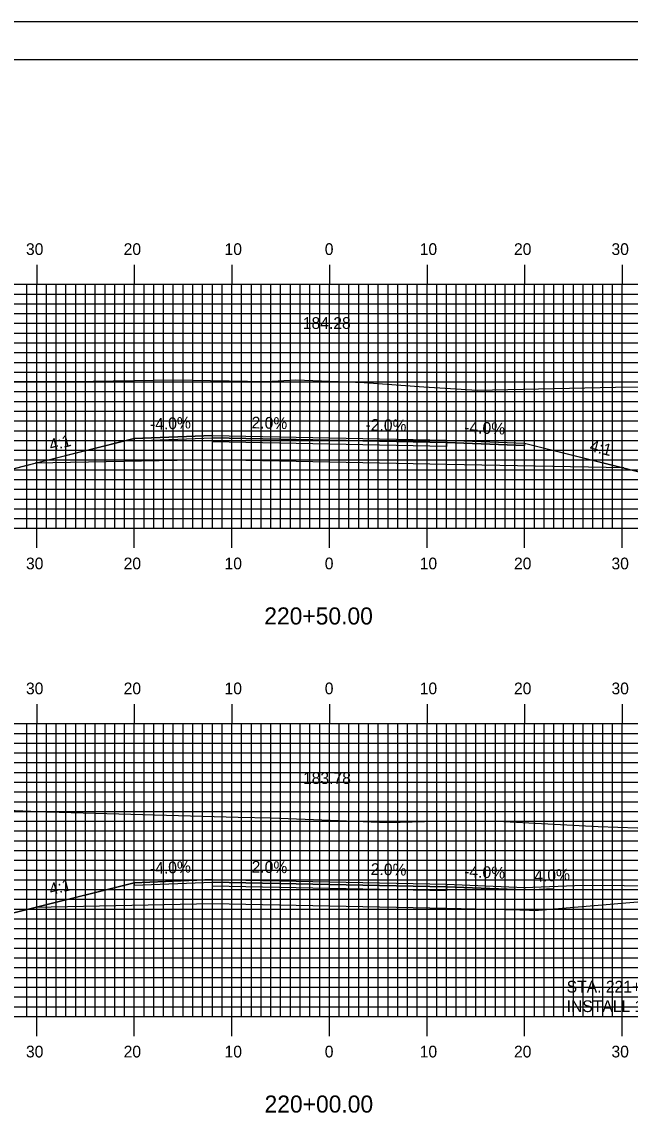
# Model space of a CAD drawing. Extents: x 1797207 to 1797550, y 442591 to 442811.
# Drawn here: x 1797341.4 to 1797403.7, y 442698.5 to 442810.5 of the extents above; entities that cross this region are included whole.
import ezdxf

# ---------------------------------------------------------------- set-up
doc = ezdxf.new("R2010")
doc.units = 0
for name, color, linetype in [('ANNOTATION', 7, 'Continuous'), ('BORDER', 7, 'Continuous'), ('D_Roadway_Centerline', 7, 'Continuous'), ('D_Roadway_Centerline_Text', 7, 'Continuous'), ('D_Roadway_Edge_Shoulder', 7, 'Continuous'), ('D_Roadway_Edge_TW', 7, 'Continuous'), ('D_Roadway_Pavement', 7, 'Continuous'), ('D_Roadway_SlopeLines', 7, 'Continuous'), ('D_Roadway_SubGrade', 7, 'Continuous'), ('H_V ANNOTATION', 7, 'Continuous'), ('MAJOR', 7, 'Continuous'), ('MINOR', 7, 'Continuous'), ('PLOT BOUNDARY', 7, 'Continuous'), ('S_Roadway_Centerline', 7, 'Continuous')]:
    doc.layers.add(name, color=color, linetype=linetype)

msp = doc.modelspace()

# ---------------------------------------------------------------- linework, layer by layer
at = {"layer": 'BORDER'}
msp.add_lwpolyline([(1797223.33, 442596.67), (1797543.33, 442596.67), (1797543.33, 442806.67), (1797223.33, 442806.67)], close=True, dxfattribs=at)
at = {"layer": 'D_Roadway_Centerline'}
for points in [[(1797294.18, 442774.92), (1797295.43, 442774.81), (1797296.68, 442774.55), (1797297.93, 442774.15), (1797299.18, 442773.6), (1797310.36, 442768.01), (1797324.58, 442767.87), (1797338.76, 442764.33), (1797342.76, 442765.33), (1797352.93, 442767.87), (1797360.93, 442768.19), (1797372.93, 442767.95), (1797384.93, 442767.71), (1797392.93, 442767.39), (1797403.11, 442764.85), (1797407.11, 442763.85), (1797421.28, 442767.39), (1797440.76, 442767.58), (1797446.68, 442770.54), (1797447.93, 442771.08), (1797449.18, 442771.45), (1797450.43, 442771.65), (1797451.68, 442771.68)], [(1797282.93, 442731.5), (1797284.18, 442731.38), (1797285.43, 442731.11), (1797286.68, 442730.7), (1797287.93, 442730.15), (1797303.2, 442722.51), (1797317.5, 442722.37), (1797338.76, 442718.83), (1797342.76, 442719.83), (1797352.93, 442722.37), (1797360.93, 442722.69), (1797372.93, 442722.45), (1797384.93, 442722.21), (1797392.93, 442721.89)]]:
    msp.add_lwpolyline(points, dxfattribs=at)
at = {"layer": 'D_Roadway_Edge_Shoulder'}
for points in [[(1797360.93, 442768.19), (1797352.93, 442767.87), (1797352.93, 442767.62), (1797360.93, 442767.94)], [(1797384.93, 442767.71), (1797392.93, 442767.39), (1797392.93, 442767.14), (1797384.93, 442767.46)], [(1797360.93, 442722.69), (1797352.93, 442722.37), (1797352.93, 442722.12), (1797360.93, 442722.44)], [(1797384.93, 442722.21), (1797392.93, 442721.89), (1797392.93, 442721.64), (1797384.93, 442721.96)]]:
    msp.add_lwpolyline(points, close=True, dxfattribs=at)
at = {"layer": 'D_Roadway_Edge_TW'}
for points in [[(1797360.93, 442767.94), (1797360.93, 442768.19), (1797372.93, 442767.95), (1797384.93, 442767.71), (1797384.93, 442767.46), (1797372.93, 442767.7)], [(1797360.93, 442722.44), (1797360.93, 442722.69), (1797372.93, 442722.45), (1797384.93, 442722.21), (1797384.93, 442721.96), (1797372.93, 442722.2)]]:
    msp.add_lwpolyline(points, close=True, dxfattribs=at)
at = {"layer": 'D_Roadway_Pavement'}
for points in [[(1797360.93, 442767.52), (1797360.93, 442767.94), (1797372.93, 442767.7), (1797384.93, 442767.46), (1797384.93, 442767.04), (1797372.93, 442767.28)], [(1797360.93, 442722.02), (1797360.93, 442722.44), (1797372.93, 442722.2), (1797384.93, 442721.96), (1797384.93, 442721.54), (1797372.93, 442721.78)]]:
    msp.add_lwpolyline(points, close=True, dxfattribs=at)
at = {"layer": 'D_Roadway_SlopeLines'}
for points in [[(1797352.93, 442767.87), (1797338.76, 442764.33)], [(1797392.93, 442767.39), (1797407.11, 442763.85)], [(1797352.93, 442722.37), (1797338.76, 442718.83)]]:
    msp.add_lwpolyline(points, dxfattribs=at)
at = {"layer": 'D_Roadway_SubGrade'}
msp.add_line((1797392.93, 442721.64), (1797395.93, 442721.76), dxfattribs=at)
msp.add_lwpolyline([(1797360.93, 442765.69), (1797342.76, 442765.33), (1797352.93, 442767.87), (1797352.93, 442767.62), (1797360.93, 442767.94), (1797372.93, 442767.7), (1797384.93, 442767.46), (1797392.93, 442767.14), (1797392.93, 442767.39), (1797403.11, 442764.85), (1797384.93, 442765.21), (1797372.93, 442765.45)], close=True, dxfattribs=at)
for points in [[(1797393.93, 442719.53), (1797384.93, 442719.71), (1797372.93, 442719.95), (1797360.93, 442720.19), (1797342.76, 442719.83), (1797352.93, 442722.37), (1797352.93, 442722.12), (1797360.93, 442722.44), (1797372.93, 442722.2), (1797384.93, 442721.96), (1797392.93, 442721.64), (1797392.93, 442721.89)], [(1797392.93, 442721.89), (1797398.93, 442722.13), (1797428.37, 442721.89)], [(1797395.93, 442721.76), (1797395.93, 442722.01)], [(1797393.43, 442719.54), (1797393.93, 442719.53), (1797404.93, 442720.46), (1797419.07, 442720.34)]]:
    msp.add_lwpolyline(points, dxfattribs=at)
at = {"layer": 'MAJOR'}
for p, q in [((1797342.93, 442785.67), (1797342.93, 442783.67)), ((1797352.93, 442785.67), (1797352.93, 442783.67)), ((1797362.93, 442785.67), (1797362.93, 442783.67)), ((1797372.93, 442785.67), (1797372.93, 442783.67)), ((1797382.93, 442785.67), (1797382.93, 442783.67)), ((1797392.93, 442785.67), (1797392.93, 442783.67)), ((1797402.93, 442785.67), (1797402.93, 442783.67)), ((1797232.93, 442783.67), (1797512.93, 442783.67)), ((1797232.93, 442783.67), (1797512.93, 442783.67)), ((1797342.93, 442758.67), (1797342.93, 442783.67)), ((1797352.93, 442758.67), (1797352.93, 442783.67)), ((1797362.93, 442758.67), (1797362.93, 442783.67)), ((1797372.93, 442758.67), (1797372.93, 442783.67)), ((1797382.93, 442758.67), (1797382.93, 442783.67)), ((1797392.93, 442758.67), (1797392.93, 442783.67)), ((1797402.93, 442758.67), (1797402.93, 442783.67)), ((1797232.93, 442778.67), (1797512.93, 442778.67)), ((1797232.93, 442773.67), (1797512.93, 442773.67)), ((1797232.93, 442768.67), (1797512.93, 442768.67)), ((1797232.93, 442763.67), (1797512.93, 442763.67)), ((1797232.93, 442758.67), (1797512.93, 442758.67)), ((1797232.93, 442758.67), (1797512.93, 442758.67)), ((1797342.93, 442756.66), (1797342.93, 442758.67)), ((1797352.93, 442756.66), (1797352.93, 442758.67)), ((1797362.93, 442756.66), (1797362.93, 442758.67)), ((1797372.93, 442756.66), (1797372.93, 442758.67)), ((1797382.93, 442756.66), (1797382.93, 442758.67)), ((1797392.93, 442756.66), (1797392.93, 442758.67)), ((1797402.93, 442756.66), (1797402.93, 442758.67)), ((1797342.93, 442740.67), (1797342.93, 442738.67)), ((1797352.93, 442740.67), (1797352.93, 442738.67)), ((1797362.93, 442740.67), (1797362.93, 442738.67)), ((1797372.93, 442740.67), (1797372.93, 442738.67)), ((1797382.93, 442740.67), (1797382.93, 442738.67)), ((1797392.93, 442740.67), (1797392.93, 442738.67)), ((1797402.93, 442740.67), (1797402.93, 442738.67)), ((1797232.93, 442738.67), (1797512.93, 442738.67)), ((1797232.93, 442738.67), (1797512.93, 442738.67)), ((1797342.93, 442708.67), (1797342.93, 442738.67)), ((1797352.93, 442708.67), (1797352.93, 442738.67)), ((1797362.93, 442708.67), (1797362.93, 442738.67)), ((1797372.93, 442708.67), (1797372.93, 442738.67)), ((1797382.93, 442708.67), (1797382.93, 442738.67)), ((1797392.93, 442708.67), (1797392.93, 442738.67)), ((1797402.93, 442708.67), (1797402.93, 442738.67)), ((1797232.93, 442733.67), (1797512.93, 442733.67)), ((1797232.93, 442728.67), (1797512.93, 442728.67)), ((1797232.93, 442723.67), (1797512.93, 442723.67)), ((1797232.93, 442718.67), (1797512.93, 442718.67)), ((1797232.93, 442713.67), (1797512.93, 442713.67)), ((1797232.93, 442708.67), (1797512.93, 442708.67)), ((1797232.93, 442708.67), (1797512.93, 442708.67)), ((1797342.93, 442706.66), (1797342.93, 442708.67)), ((1797352.93, 442706.66), (1797352.93, 442708.67)), ((1797362.93, 442706.66), (1797362.93, 442708.67)), ((1797372.93, 442706.66), (1797372.93, 442708.67)), ((1797382.93, 442706.66), (1797382.93, 442708.67)), ((1797392.93, 442706.66), (1797392.93, 442708.67)), ((1797402.93, 442706.66), (1797402.93, 442708.67))]:
    msp.add_line(p, q, dxfattribs=at)
at = {"layer": 'MINOR'}
for p, q in [((1797341.93, 442758.67), (1797341.93, 442783.67)), ((1797343.93, 442758.67), (1797343.93, 442783.67)), ((1797344.93, 442758.67), (1797344.93, 442783.67)), ((1797345.93, 442758.67), (1797345.93, 442783.67)), ((1797346.93, 442758.67), (1797346.93, 442783.67)), ((1797347.93, 442758.67), (1797347.93, 442783.67)), ((1797348.93, 442758.67), (1797348.93, 442783.67)), ((1797349.93, 442758.67), (1797349.93, 442783.67)), ((1797350.93, 442758.67), (1797350.93, 442783.67)), ((1797351.93, 442758.67), (1797351.93, 442783.67)), ((1797353.93, 442758.67), (1797353.93, 442783.67)), ((1797354.93, 442758.67), (1797354.93, 442783.67)), ((1797355.93, 442758.67), (1797355.93, 442783.67)), ((1797356.93, 442758.67), (1797356.93, 442783.67)), ((1797357.93, 442758.67), (1797357.93, 442783.67)), ((1797358.93, 442758.67), (1797358.93, 442783.67)), ((1797359.93, 442758.67), (1797359.93, 442783.67)), ((1797360.93, 442758.67), (1797360.93, 442783.67)), ((1797361.93, 442758.67), (1797361.93, 442783.67)), ((1797363.93, 442758.67), (1797363.93, 442783.67)), ((1797364.93, 442758.67), (1797364.93, 442783.67)), ((1797365.93, 442758.67), (1797365.93, 442783.67)), ((1797366.93, 442758.67), (1797366.93, 442783.67)), ((1797367.93, 442758.67), (1797367.93, 442783.67)), ((1797368.93, 442758.67), (1797368.93, 442783.67)), ((1797369.93, 442758.67), (1797369.93, 442783.67)), ((1797370.93, 442758.67), (1797370.93, 442783.67)), ((1797371.93, 442758.67), (1797371.93, 442783.67)), ((1797373.93, 442758.67), (1797373.93, 442783.67)), ((1797374.93, 442758.67), (1797374.93, 442783.67)), ((1797375.93, 442758.67), (1797375.93, 442783.67)), ((1797376.93, 442758.67), (1797376.93, 442783.67)), ((1797377.93, 442758.67), (1797377.93, 442783.67)), ((1797378.93, 442758.67), (1797378.93, 442783.67)), ((1797379.93, 442758.67), (1797379.93, 442783.67)), ((1797380.93, 442758.67), (1797380.93, 442783.67)), ((1797381.93, 442758.67), (1797381.93, 442783.67)), ((1797383.93, 442758.67), (1797383.93, 442783.67)), ((1797384.93, 442758.67), (1797384.93, 442783.67)), ((1797385.93, 442758.67), (1797385.93, 442783.67)), ((1797386.93, 442758.67), (1797386.93, 442783.67)), ((1797387.93, 442758.67), (1797387.93, 442783.67)), ((1797388.93, 442758.67), (1797388.93, 442783.67)), ((1797389.93, 442758.67), (1797389.93, 442783.67)), ((1797390.93, 442758.67), (1797390.93, 442783.67)), ((1797391.93, 442758.67), (1797391.93, 442783.67)), ((1797393.93, 442758.67), (1797393.93, 442783.67)), ((1797394.93, 442758.67), (1797394.93, 442783.67)), ((1797395.93, 442758.67), (1797395.93, 442783.67)), ((1797396.93, 442758.67), (1797396.93, 442783.67)), ((1797397.93, 442758.67), (1797397.93, 442783.67)), ((1797398.93, 442758.67), (1797398.93, 442783.67)), ((1797399.93, 442758.67), (1797399.93, 442783.67)), ((1797400.93, 442758.67), (1797400.93, 442783.67)), ((1797401.93, 442758.67), (1797401.93, 442783.67)), ((1797232.93, 442782.67), (1797512.93, 442782.67)), ((1797232.93, 442781.67), (1797512.93, 442781.67)), ((1797232.93, 442780.67), (1797512.93, 442780.67)), ((1797232.93, 442779.67), (1797512.93, 442779.67)), ((1797232.93, 442777.67), (1797512.93, 442777.67)), ((1797232.93, 442776.67), (1797512.93, 442776.67)), ((1797232.93, 442775.67), (1797512.93, 442775.67)), ((1797232.93, 442774.67), (1797512.93, 442774.67)), ((1797232.93, 442772.67), (1797512.93, 442772.67)), ((1797232.93, 442771.67), (1797512.93, 442771.67)), ((1797232.93, 442770.67), (1797512.93, 442770.67)), ((1797232.93, 442769.67), (1797512.93, 442769.67)), ((1797232.93, 442767.67), (1797512.93, 442767.67)), ((1797232.93, 442766.67), (1797512.93, 442766.67)), ((1797232.93, 442765.67), (1797512.93, 442765.67)), ((1797232.93, 442764.67), (1797512.93, 442764.67)), ((1797232.93, 442762.67), (1797512.93, 442762.67)), ((1797232.93, 442761.67), (1797512.93, 442761.67)), ((1797232.93, 442760.67), (1797512.93, 442760.67)), ((1797232.93, 442759.67), (1797512.93, 442759.67)), ((1797341.93, 442708.67), (1797341.93, 442738.67)), ((1797343.93, 442708.67), (1797343.93, 442738.67)), ((1797344.93, 442708.67), (1797344.93, 442738.67)), ((1797345.93, 442708.67), (1797345.93, 442738.67)), ((1797346.93, 442708.67), (1797346.93, 442738.67)), ((1797347.93, 442708.67), (1797347.93, 442738.67)), ((1797348.93, 442708.67), (1797348.93, 442738.67)), ((1797349.93, 442708.67), (1797349.93, 442738.67)), ((1797350.93, 442708.67), (1797350.93, 442738.67)), ((1797351.93, 442708.67), (1797351.93, 442738.67)), ((1797353.93, 442708.67), (1797353.93, 442738.67)), ((1797354.93, 442708.67), (1797354.93, 442738.67)), ((1797355.93, 442708.67), (1797355.93, 442738.67)), ((1797356.93, 442708.67), (1797356.93, 442738.67)), ((1797357.93, 442708.67), (1797357.93, 442738.67)), ((1797358.93, 442708.67), (1797358.93, 442738.67)), ((1797359.93, 442708.67), (1797359.93, 442738.67)), ((1797360.93, 442708.67), (1797360.93, 442738.67)), ((1797361.93, 442708.67), (1797361.93, 442738.67)), ((1797363.93, 442708.67), (1797363.93, 442738.67)), ((1797364.93, 442708.67), (1797364.93, 442738.67)), ((1797365.93, 442708.67), (1797365.93, 442738.67)), ((1797366.93, 442708.67), (1797366.93, 442738.67)), ((1797367.93, 442708.67), (1797367.93, 442738.67)), ((1797368.93, 442708.67), (1797368.93, 442738.67)), ((1797369.93, 442708.67), (1797369.93, 442738.67)), ((1797370.93, 442708.67), (1797370.93, 442738.67)), ((1797371.93, 442708.67), (1797371.93, 442738.67)), ((1797373.93, 442708.67), (1797373.93, 442738.67)), ((1797374.93, 442708.67), (1797374.93, 442738.67)), ((1797375.93, 442708.67), (1797375.93, 442738.67)), ((1797376.93, 442708.67), (1797376.93, 442738.67)), ((1797377.93, 442708.67), (1797377.93, 442738.67)), ((1797378.93, 442708.67), (1797378.93, 442738.67)), ((1797379.93, 442708.67), (1797379.93, 442738.67)), ((1797380.93, 442708.67), (1797380.93, 442738.67)), ((1797381.93, 442708.67), (1797381.93, 442738.67)), ((1797383.93, 442708.67), (1797383.93, 442738.67)), ((1797384.93, 442708.67), (1797384.93, 442738.67)), ((1797385.93, 442708.67), (1797385.93, 442738.67)), ((1797386.93, 442708.67), (1797386.93, 442738.67)), ((1797387.93, 442708.67), (1797387.93, 442738.67)), ((1797388.93, 442708.67), (1797388.93, 442738.67)), ((1797389.93, 442708.67), (1797389.93, 442738.67)), ((1797390.93, 442708.67), (1797390.93, 442738.67)), ((1797391.93, 442708.67), (1797391.93, 442738.67)), ((1797393.93, 442708.67), (1797393.93, 442738.67)), ((1797394.93, 442708.67), (1797394.93, 442738.67)), ((1797395.93, 442708.67), (1797395.93, 442738.67)), ((1797396.93, 442708.67), (1797396.93, 442738.67)), ((1797397.93, 442708.67), (1797397.93, 442738.67)), ((1797398.93, 442708.67), (1797398.93, 442738.67)), ((1797399.93, 442708.67), (1797399.93, 442738.67)), ((1797400.93, 442708.67), (1797400.93, 442738.67)), ((1797401.93, 442708.67), (1797401.93, 442738.67)), ((1797232.93, 442737.67), (1797512.93, 442737.67)), ((1797232.93, 442736.67), (1797512.93, 442736.67)), ((1797232.93, 442735.67), (1797512.93, 442735.67)), ((1797232.93, 442734.67), (1797512.93, 442734.67)), ((1797232.93, 442732.67), (1797512.93, 442732.67)), ((1797232.93, 442731.67), (1797512.93, 442731.67)), ((1797232.93, 442730.67), (1797512.93, 442730.67)), ((1797232.93, 442729.67), (1797512.93, 442729.67)), ((1797232.93, 442727.67), (1797512.93, 442727.67)), ((1797232.93, 442726.67), (1797512.93, 442726.67)), ((1797232.93, 442725.67), (1797512.93, 442725.67)), ((1797232.93, 442724.67), (1797512.93, 442724.67)), ((1797232.93, 442722.67), (1797512.93, 442722.67)), ((1797232.93, 442721.67), (1797512.93, 442721.67)), ((1797232.93, 442720.67), (1797512.93, 442720.67)), ((1797232.93, 442719.67), (1797512.93, 442719.67)), ((1797232.93, 442717.67), (1797512.93, 442717.67)), ((1797232.93, 442716.67), (1797512.93, 442716.67)), ((1797232.93, 442715.67), (1797512.93, 442715.67)), ((1797232.93, 442714.67), (1797512.93, 442714.67)), ((1797232.93, 442712.67), (1797512.93, 442712.67)), ((1797232.93, 442711.67), (1797512.93, 442711.67)), ((1797232.93, 442710.67), (1797512.93, 442710.67)), ((1797232.93, 442709.67), (1797512.93, 442709.67))]:
    msp.add_line(p, q, dxfattribs=at)
at = {"layer": 'PLOT BOUNDARY'}
msp.add_lwpolyline([(1797207.14, 442590.55), (1797547.14, 442590.55), (1797547.14, 442810.55), (1797207.14, 442810.55)], close=True, dxfattribs=at)
at = {"layer": 'S_Roadway_Centerline'}
for points in [[(1797338.85, 442773.76), (1797346.65, 442773.7), (1797356.94, 442773.88), (1797366.43, 442773.72), (1797369.5, 442773.89), (1797376.5, 442773.61), (1797382.61, 442773.17), (1797388.07, 442772.81), (1797402.23, 442773.12), (1797407.7, 442773.21), (1797408.6, 442773.19), (1797410.01, 442773.08), (1797420.37, 442772.1), (1797428.58, 442772.22), (1797432.61, 442772.33), (1797438.13, 442772.23), (1797445.15, 442772.08), (1797449.51, 442771.77), (1797463.24, 442771.2), (1797470.07, 442771.1)], [(1797331.86, 442730.14), (1797343.1, 442729.66), (1797343.99, 442729.62), (1797345.24, 442729.58), (1797363.56, 442729.09), (1797366.97, 442729), (1797371.3, 442728.84), (1797378.9, 442728.53), (1797383.95, 442728.67), (1797390.15, 442728.68), (1797400.45, 442728.11), (1797404.48, 442727.99), (1797422.18, 442727.99), (1797424.47, 442727.99), (1797424.67, 442728), (1797424.96, 442728), (1797437.25, 442727.65), (1797445.58, 442727.73), (1797449.83, 442727.56), (1797455.01, 442727.25), (1797461.14, 442726.89), (1797466.94, 442726.6)]]:
    msp.add_lwpolyline(points, dxfattribs=at)

# ---------------------------------------------------------------- texts
at = {"layer": 'ANNOTATION'}
for s, rotation, p in [('-4.0%', 2.2906, (1797354.56, 442768.74)), ('2.0%', 358.8542, (1797364.94, 442768.91)), ('-2.0%', 358.8542, (1797376.62, 442768.68)), ('-4.0%', 357.7094, (1797386.72, 442768.44)), ('4:1', 14.0362, (1797344.38, 442766.59)), ('4:1', 345.9638, (1797399.52, 442766.6)), ('2.0%', 358.8542, (1797364.94, 442723.41)), ('-4.0%', 2.2906, (1797354.56, 442723.24)), ('-2.0%', 358.8542, (1797376.62, 442723.18)), ('-4.0%', 357.7094, (1797386.72, 442722.94)), ('4.0%', 2.2906, (1797393.94, 442722.46)), ('4:1', 14.0362, (1797344.38, 442721.09))]:
    msp.add_text(s, height=1.2, rotation=rotation, dxfattribs=at).set_placement(p)
for s, p in [("STA. 221+88.00, 34.4' RT. TO 222+12.00, 34.2' RT.", (1797397.24, 442711.12)), ('INSTALL 18" X 24\' OPT. I CULVERT PIPE', (1797397.24, 442709.12))]:
    msp.add_text(s, height=1.2, dxfattribs=at).set_placement(p)
at = {"layer": 'D_Roadway_Centerline'}
for s, p in [('C', (1797372.93, 442767.95)), ('L', (1797372.93, 442767.94)), ('C', (1797372.93, 442722.45)), ('L', (1797372.93, 442722.44))]:
    msp.add_text(s, height=0.0146, dxfattribs=at).set_placement(p)
at = {"layer": 'D_Roadway_Centerline_Text'}
for s, p in [('184.28', (1797370.2, 442779.1)), ('183.78', (1797370.22, 442732.48))]:
    msp.add_text(s, height=1.2, dxfattribs=at).set_placement(p)
at = {"layer": 'H_V ANNOTATION'}
for s, height, p in [('30', 1.2, (1797341.83, 442786.67)), ('20', 1.2, (1797351.84, 442786.67)), ('10', 1.2, (1797362.18, 442786.67)), ('0', 1.2, (1797372.45, 442786.67)), ('10', 1.2, (1797382.18, 442786.67)), ('20', 1.2, (1797391.84, 442786.67)), ('30', 1.2, (1797401.83, 442786.67)), ('30', 1.2, (1797341.83, 442754.47)), ('20', 1.2, (1797351.84, 442754.47)), ('10', 1.2, (1797362.18, 442754.47)), ('0', 1.2, (1797372.45, 442754.47)), ('10', 1.2, (1797382.18, 442754.47)), ('20', 1.2, (1797391.84, 442754.47)), ('30', 1.2, (1797401.83, 442754.47)), ('220+50.00', 1.75, (1797366.25, 442748.82)), ('30', 1.2, (1797341.83, 442741.67)), ('20', 1.2, (1797351.84, 442741.67)), ('10', 1.2, (1797362.18, 442741.67)), ('0', 1.2, (1797372.45, 442741.67)), ('10', 1.2, (1797382.18, 442741.67)), ('20', 1.2, (1797391.84, 442741.67)), ('30', 1.2, (1797401.83, 442741.67)), ('30', 1.2, (1797341.83, 442704.47)), ('20', 1.2, (1797351.84, 442704.47)), ('10', 1.2, (1797362.18, 442704.47)), ('0', 1.2, (1797372.45, 442704.47)), ('10', 1.2, (1797382.18, 442704.47)), ('20', 1.2, (1797391.84, 442704.47)), ('30', 1.2, (1797401.83, 442704.47)), ('220+00.00', 1.75, (1797366.28, 442698.82))]:
    msp.add_text(s, height=height, dxfattribs=at).set_placement(p)

doc.saveas('drawing.dxf')
